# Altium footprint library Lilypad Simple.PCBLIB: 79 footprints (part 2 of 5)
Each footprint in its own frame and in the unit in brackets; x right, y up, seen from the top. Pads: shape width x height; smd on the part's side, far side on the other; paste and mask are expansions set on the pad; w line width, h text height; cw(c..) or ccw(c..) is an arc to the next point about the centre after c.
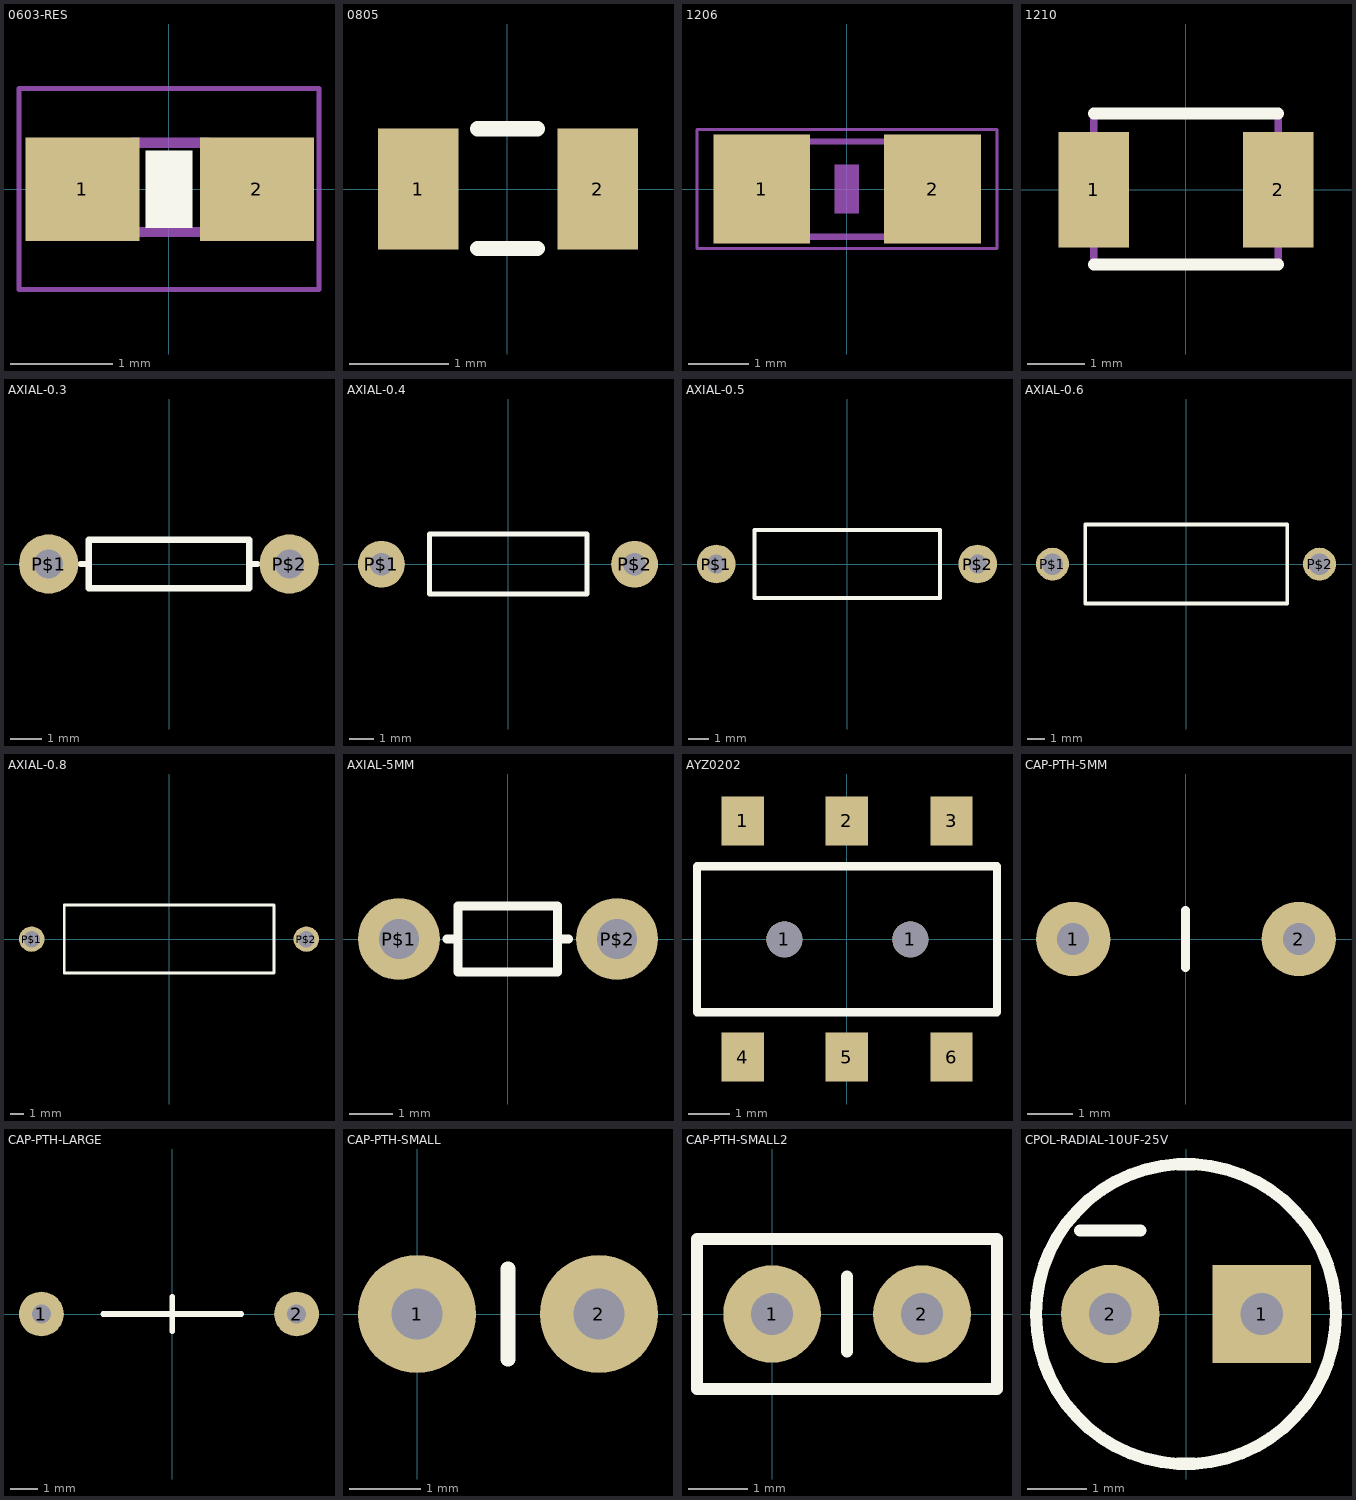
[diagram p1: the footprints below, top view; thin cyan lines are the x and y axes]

## 0603-RES [mil]
pads (2):
  rect 44x40 smd: 1(-33.46,0) 2(34,0)
Top Overlay:
  rectangle: -9,-15 9,15
Assembly Text Top:
  rectangle: -7.87,-11.81 8,12
Courtyard Bottom:
  rectangle: -33,-18.5 -13.31,19
  rectangle: 13,-18.5 33,19
  lines w4: -14.02,-16.5 15,-16.5 ; -14.02,18 15,18
Mechanical 37:
  lines w2: -57.99,-38.7 58,-38.7 58,39 -57.99,39 -57.99,-38.7

## 0805 [mil]
pads (2):
  rect 32x48 smd: 1(-35.43,0) 2(36,0)
Top Overlay:
  lines w6: -11.81,-23.62 12,-23.62 ; -11.81,24 12,24

## 1206 [mil]
pads (2):
  rect 63x71 smd: 1(-55.12,0) 2(56,0)
Assembly Text Top:
  rectangle: -7.87,-15.75 8,16
Courtyard Bottom:
  rectangle: -67,-33.5 -37.47,34
  rectangle: 38,-33.43 67,34
  lines w4: -37.99,-30.98 38,-30.98 ; -37.99,31 38,31
Mechanical 37:
  lines w2: -97.36,-38.7 98,-38.7 98,39 -97.36,39 -97.36,-38.7

## 1210 [mil]
pads (2):
  rect 48x79 smd: 1(-62.99,0) 2(63,0)
Top Overlay:
  lines w8: -62.99,-51.18 63,-51.18 ; -62.99,52 63,52
Courtyard Bottom:
  lines w5: -62.99,-51.18 63,-51.18 63,52 -62.99,52 -62.99,-51.18

## AXIAL-0.3 [mil]
pads (2):
  round 74 hole 36: P$1(-150,0) P$2(150,0)
Top Overlay:
  lines w8: -110,0 -100,0 ; 110,0 100,0 ; -100,0 -100,-30 100,-30 100,0 ; -100,0 -100,30 100,30 100,0

## AXIAL-0.4 [mil]
pads (2):
  round 74 hole 36: P$1(-200,0) P$2(200,0)
Top Overlay:
  lines w8: -124.02,-47.24 -124.02,48 125,48 125,-47.24 -124.02,-47.24

## AXIAL-0.5 [mil]
pads (2):
  round 74 hole 36: P$1(-250,0) P$2(250,0)
Top Overlay:
  lines w8: -177.17,-64.96 -177.17,65 178,65 178,-64.96 -177.17,-64.96

## AXIAL-0.6 [mil]
pads (2):
  round 74 hole 48: P$1(-300,0) P$2(300,0)
Top Overlay:
  lines w8: -226.38,-88.58 -226.38,89 227,89 227,-88.58 -226.38,-88.58

## AXIAL-0.8 [mil]
pads (2):
  round 74 hole 48: P$1(-400,0) P$2(400,0)
Top Overlay:
  lines w8: -305.12,-98.43 -305.12,99 306,99 306,-98.43 -305.12,-98.43

## AXIAL-5MM [mil]
pads (2):
  round 74 hole 36: P$1(-98.43,0) P$2(99,0)
Top Overlay:
  lines w8: -54.88,0 -44.88,0 ; 55,0 45,0 ; -44.88,0 -44.88,-30 45,-30 45,0 ; -44.88,0 -44.88,30 45,30 45,0

## AYZ0202 [mil]
pads (8):
  rect 40x46 smd: 1(-98.43,112) 2(0,112) 3(99,112) 4(-98.43,-111.22) 5(0,-111.22) 6(99,-111.22)
  round 34 hole 34: 1(-59.06,0) 1(60,0)
Top Overlay:
  lines w8: -141.73,-68.9 -141.73,69 142,69 142,-68.9 -141.73,-68.9

## CAP-PTH-5MM [mil]
pads (2):
  round 65 hole 28: 1(-98.43,0) 2(99,0)
Top Overlay:
  lines w8: 0,-25 0,25

## CAP-PTH-LARGE [mil]
pads (2):
  round 65 hole 28: 1(-190,0) 2(180,0)
Top Overlay:
  lines w8: -100,0 0,0 ; 0,-25 0,0 ; 0,25 0,0 ; 100,0 0,0

## CAP-PTH-SMALL [mil]
pads (2):
  round 65 hole 28: 1(0,0) 2(100,0)
Top Overlay:
  lines w8: 50,-25 50,25

## CAP-PTH-SMALL2 [mil]
pads (2):
  round 65 hole 28: 1(0,0) 2(100,0)
Top Overlay:
  lines w8: 50,-25 50,25 ; -50,-50 150,-50 150,50 -50,50 -50,-50

## CPOL-RADIAL-10UF-25V [mil]
pads (2):
  rect 65x65 hole 28: 1(50,0)
  round 65 hole 28: 2(-50,0)
Top Overlay:
  circle w8: c0,0 r99
  lines w8: -70,55 -30,55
